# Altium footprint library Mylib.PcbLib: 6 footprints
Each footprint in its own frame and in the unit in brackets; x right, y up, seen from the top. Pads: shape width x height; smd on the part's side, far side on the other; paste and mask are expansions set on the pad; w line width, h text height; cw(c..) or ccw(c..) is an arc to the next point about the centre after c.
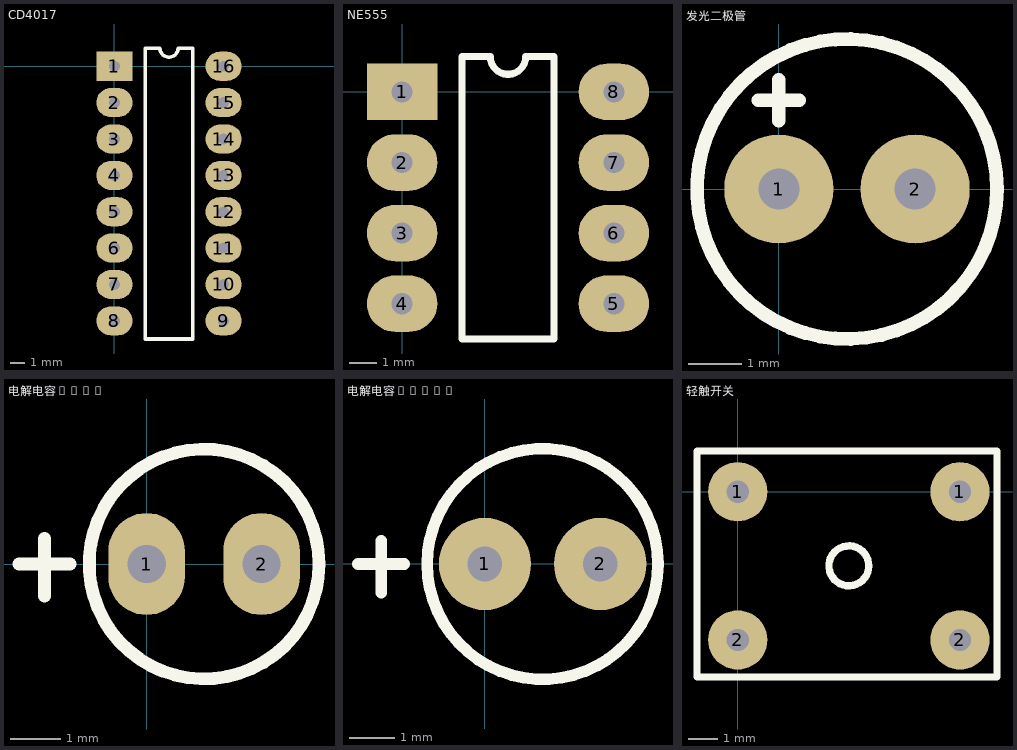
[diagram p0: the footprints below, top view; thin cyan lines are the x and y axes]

## CD4017 [mil]
pads (16):
  rect 100x80 hole 30: 1(0,0)
  oval 100x80 hole 30: 2(0,-100) 3(0,-200) 4(0,-300) 5(0,-400) 6(0,-500) 7(0,-600) 8(0,-700) 9(300,-700) 10(300,-600) 11(300,-500) 12(300,-400) 13(300,-300) 14(300,-200) 15(300,-100) 16(300,0)
Top Overlay:
  lines w10: 85,-750 85,50 125,50 ccw(c150,50) 175,50 215,50 215,-750 85,-750

## NE555 [mil]
pads (8):
  rect 100x80 hole 30: 1(0,0)
  oval 100x80 hole 30: 2(0,-100) 3(0,-200) 4(0,-300) 5(300,-300) 6(300,-200) 7(300,-100) 8(300,0)
Top Overlay:
  lines w10: 85,-350 215,-350 215,50 175,50 cw(c150,50) 125,50 85,50 85,-350

## 发光二极管 [mil]
pads (2):
  round 80 hole 30: 1(0,0) 2(100,0)
Top Overlay:
  circle w10: c50,0 r110
  lines w10: -15,65 15,65 ; 0,50 0,80

## 电解电容47uF [mil]
pads (2):
  oval 60x80 hole 30: 1(0,0) 2(90,0)
Top Overlay:
  circle w10: c45,0 r90
  lines w10: -100,0 -60,0 ; -80,-25 -80,20

## 电解电容100uF [mil]
pads (2):
  round 80 hole 30: 1(0,0) 2(100,0)
Top Overlay:
  circle w10: c50,0 r100
  lines w10: -110,0 -70,0 ; -90,-25 -90,20

## 轻触开关 [mil]
pads (4):
  round 80 hole 30: 1(0,0) 1(300,0) 2(0,-200) 2(300,-200)
Top Overlay:
  circle w10: c150,-100 r26.93
  lines w10: -55,-250 350,-250 350,55 -55,55 -55,-250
